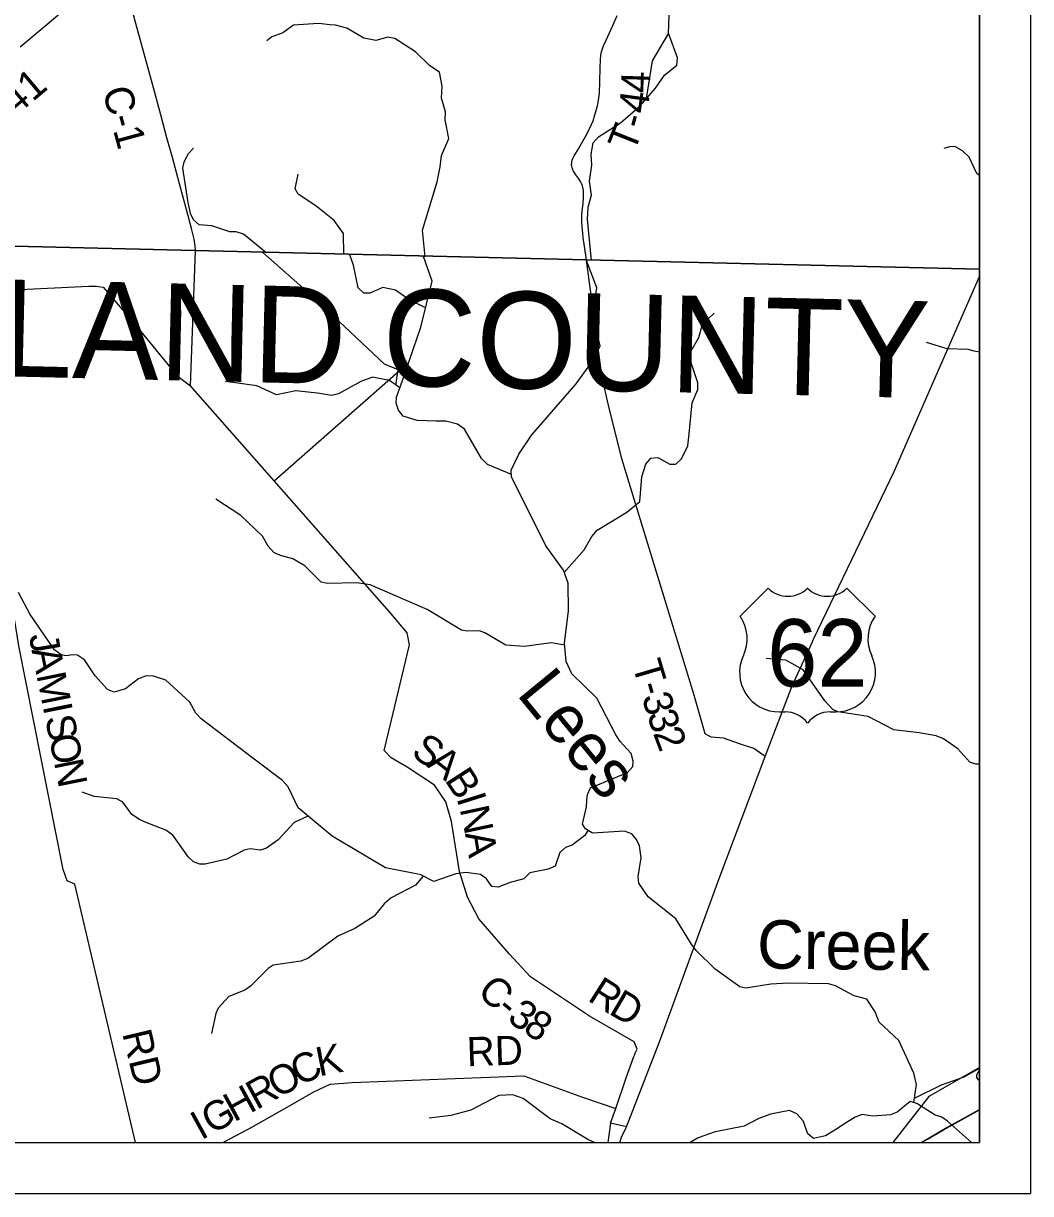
# Model space of a CAD drawing. Extents: x 0 to 34, y 0 to 22.
# Drawn here: x 7.032 to 9, y 14 to 16.287 of the extents above; entities that cross this region are included whole.
import ezdxf

# ---------------------------------------------------------------- set-up
doc = ezdxf.new("R2010")
doc.units = 0
for name, color, linetype in [('Default', 7, 'Continuous'), ('GM_X_City_Street', 7, 'Continuous'), ('GM_X_County_Road', 7, 'Continuous'), ('GM_X_County_Road_Text', 7, 'Continuous'), ('GM_X_County_Text', 7, 'Continuous'), ('GM_X_Minor_River', 7, 'Continuous'), ('GM_X_Minor_River_Text', 7, 'Continuous'), ('GM_X_State_Route', 7, 'Continuous'), ('GM_X_Township_Road', 7, 'Continuous'), ('GM_X_Township_Road_Text', 7, 'Continuous'), ('GM_X_US_Location', 7, 'Continuous'), ('GM_X_US_Route', 7, 'Continuous'), ('GM_X_US_Shield', 7, 'Continuous'), ('SH_Cut_Line', 7, 'Continuous'), ('SH_Data', 7, 'Continuous')]:
    doc.layers.add(name, color=color, linetype=linetype)

msp = doc.modelspace()

# ---------------------------------------------------------------- linework, layer by layer
at = {"layer": 'Default'}
for points in [[(8.9, 15.8067), (8.9, 19.2947), (8.3519, 19.0632), (7.2653, 18.6041), (6.6732, 18.3539), (6.6309, 18.3364), (6.5451, 17.2211), (6.5428, 17.1931), (6.4392, 15.8657), (6.5786, 15.8624), (7.3679, 15.8435), (8.1324, 15.8252)], [(4.022, 14.1), (8.9, 14.1), (8.9, 15.8067), (8.1324, 15.8252), (7.3679, 15.8435), (6.5786, 15.8624), (6.4392, 15.8657), (6.2834, 15.7529), (6.0871, 15.6176), (5.6165, 15.2674), (4.302, 14.3105), (4.1658, 14.2105)], [(8.9, 14.1643), (8.9, 14.2464), (8.8015, 14.1899), (8.7312, 14.1), (8.786, 14.1), (8.7983, 14.1072), (8.8295, 14.125)]]:
    msp.add_lwpolyline(points, close=True, dxfattribs=at)
at = {"layer": 'GM_X_City_Street'}
msp.add_lwpolyline([(8.9, 14.2204), (8.898, 14.2221), (8.8947, 14.2267), (8.8949, 14.2319), (8.9, 14.2417)], dxfattribs=at)
at = {"layer": 'GM_X_County_Road'}
for points in [[(7.3682, 15.843), (7.3678, 15.8535), (7.3674, 15.8566), (7.3657, 15.8658), (7.3612, 15.8839), (7.3542, 15.911), (7.3374, 15.974), (7.3234, 16.025), (7.3126, 16.0639), (7.3006, 16.1089), (7.2846, 16.1689), (7.2755, 16.2019), (7.2631, 16.2468), (7.2541, 16.2798), (7.2411, 16.3277), (7.2279, 16.3757), (7.2233, 16.3937), (7.221, 16.4018), (7.2199, 16.4064)], [(8.2278, 14.2742), (8.2312, 14.2825), (8.2252, 14.2966), (8.1384, 14.347), (8.0228, 14.4237), (7.9819, 14.4677), (7.9219, 14.5373), (7.8997, 14.5792), (7.884, 14.6295), (7.8686, 14.7276), (7.8578, 14.7657), (7.8352, 14.7985), (7.7821, 14.8334), (7.751, 14.8519), (7.737, 14.8664), (7.7538, 14.9366), (7.7866, 15.0728), (7.7818, 15.096), (7.7478, 15.1369), (7.522, 15.3933), (7.3588, 15.5787), (7.3682, 15.843)], [(8.2107, 14.1307), (8.1793, 14.1375), (8.1894, 14.1666), (8.21, 14.2261), (8.2251, 14.2678), (8.2262, 14.2705), (8.2278, 14.2742)], [(8.1975, 14.1), (8.2011, 14.1101), (8.2107, 14.1307)]]:
    msp.add_lwpolyline(points, dxfattribs=at)
at = {"layer": 'GM_X_Minor_River'}
for points in [[(8.1422, 15.8241), (8.1346, 15.9045), (8.1356, 15.9284), (8.1419, 15.9518), (8.1384, 15.9788), (8.143, 16.0102), (8.1413, 16.0315), (8.1453, 16.0538), (8.1561, 16.0659), (8.1988, 16.0931), (8.2375, 16.1265), (8.267, 16.1611), (8.2851, 16.186), (8.3088, 16.2058), (8.3101, 16.2199), (8.2928, 16.2682), (8.2945, 16.3183)], [(7.8173, 15.831), (7.8122, 15.8834), (7.8405, 15.978), (7.8465, 16.0072), (7.8494, 16.0291), (7.8634, 16.0624), (7.8566, 16.0992), (7.8567, 16.1144), (7.8494, 16.1414), (7.8505, 16.1646), (7.8451, 16.1919), (7.8266, 16.2043), (7.7981, 16.2315), (7.7578, 16.2577), (7.7442, 16.2605), (7.7206, 16.2539), (7.6976, 16.2583), (7.6644, 16.278), (7.6417, 16.2839), (7.6315, 16.2848), (7.6088, 16.2869), (7.5599, 16.284), (7.5392, 16.269), (7.5175, 16.2613), (7.5076, 16.2534)], [(8.2928, 16.2682), (8.2608, 16.2143), (8.2492, 16.1404)], [(7.5055, 15.84), (7.4622, 15.8756), (7.4482, 15.8799), (7.4357, 15.8801), (7.4005, 15.8914), (7.3756, 15.8939), (7.3643, 15.9035), (7.3587, 15.9157), (7.3544, 15.9374), (7.3438, 16.0043), (7.3462, 16.0168), (7.3547, 16.0334), (7.3643, 16.0432)], [(8.9, 15.9902), (8.8949, 15.9938), (8.8801, 16.0262), (8.8669, 16.0385), (8.8523, 16.0466), (8.8413, 16.0464), (8.8306, 16.0431)], [(7.6581, 15.8355), (7.6578, 15.877), (7.6391, 15.9019), (7.6034, 15.9307), (7.5692, 15.9534), (7.5632, 15.9641), (7.5692, 15.9925)], [(7.7601, 15.5803), (7.7647, 15.6101), (7.7375, 15.6215), (7.5944, 15.7563), (7.5003, 15.8393)], [(7.8181, 15.7314), (7.7834, 15.7488), (7.759, 15.7662), (7.7343, 15.7711), (7.7091, 15.76), (7.6974, 15.7598), (7.6861, 15.7706), (7.6769, 15.8151), (7.6703, 15.8351)], [(7.7728, 15.5895), (7.8088, 15.6934), (7.8309, 15.7838), (7.814, 15.8316)], [(8.1125, 15.5828), (8.1473, 15.6315), (8.159, 15.6572), (8.1447, 15.7189), (8.1527, 15.7704), (8.1321, 15.8238)], [(8.3499, 15.5845), (8.3366, 15.624), (8.3345, 15.6373), (8.3366, 15.6472), (8.3517, 15.6735), (8.3593, 15.6996), (8.3816, 15.721)], [(8.9, 15.6445), (8.8896, 15.6468), (8.8779, 15.65), (8.8369, 15.6514), (8.7969, 15.6637)], [(7.7674, 15.5748), (7.7477, 15.5895), (7.7143, 15.5958), (7.6914, 15.5877), (7.6476, 15.5633), (7.6343, 15.5601), (7.607, 15.5647), (7.5648, 15.5692), (7.527, 15.5614), (7.4881, 15.5791), (7.427, 15.5876)], [(7.9858, 15.4054), (7.9388, 15.4255), (7.9272, 15.4367), (7.8938, 15.4942), (7.8803, 15.5043), (7.8576, 15.5096), (7.8378, 15.5099), (7.8017, 15.5112), (7.774, 15.5196), (7.7651, 15.5315), (7.7603, 15.5449), (7.7609, 15.557), (7.7728, 15.5895)], [(8.7716, 14.1778), (8.7769, 14.2132), (8.7716, 14.2357), (8.7429, 14.2992), (8.7039, 14.3351), (8.6962, 14.3554), (8.6799, 14.3803), (8.6552, 14.3864), (8.6186, 14.406), (8.605, 14.4103), (8.5267, 14.4115), (8.4924, 14.4094), (8.4436, 14.4014), (8.4322, 14.4039), (8.384, 14.4384), (8.3466, 14.4751), (8.3376, 14.4874), (8.3072, 14.5369), (8.2527, 14.5803), (8.2349, 14.6068), (8.2332, 14.6197), (8.2391, 14.6561), (8.2357, 14.6801), (8.2301, 14.6923), (8.2208, 14.7031), (8.2068, 14.7083), (8.144, 14.7043), (8.1304, 14.7128), (8.1245, 14.7224), (8.1322, 14.7557), (8.1332, 14.7683), (8.1341, 14.78), (8.1404, 14.7929), (8.2124, 14.8233), (8.2229, 14.8349), (8.2238, 14.8455), (8.2195, 14.8604), (8.1981, 14.8835), (8.19, 14.897), (8.1527, 14.9682), (8.104, 15.0157), (8.0929, 15.0402), (8.0897, 15.0759), (8.0975, 15.1389), (8.0965, 15.1932), (8.0874, 15.2185), (8.0531, 15.2665), (8.0465, 15.2799), (7.986, 15.4005), (7.9854, 15.4138), (8, 15.4455), (8.0257, 15.4831), (8.1125, 15.5828)], [(8.089, 15.2139), (8.1279, 15.2585), (8.1428, 15.2845), (8.1533, 15.2969), (8.2112, 15.3321), (8.2363, 15.3526), (8.2405, 15.4008), (8.2481, 15.4257), (8.2578, 15.4374), (8.2715, 15.4391), (8.2949, 15.4258), (8.3071, 15.426), (8.3183, 15.4365), (8.3301, 15.4617), (8.3318, 15.4735), (8.3327, 15.4852), (8.3386, 15.5456), (8.3497, 15.572), (8.3499, 15.5845)], [(8.0901, 15.0717), (8.0634, 15.0763), (8.0112, 15.0695), (7.9747, 15.072), (7.934, 15.0962), (7.9234, 15.0998), (7.8991, 15.0997), (7.8881, 15.1011), (7.8214, 15.142), (7.7099, 15.19), (7.6829, 15.1939), (7.6262, 15.1928), (7.6137, 15.1949), (7.5819, 15.2273), (7.5585, 15.241), (7.5343, 15.247), (7.5218, 15.2533), (7.5106, 15.2653), (7.4991, 15.2852), (7.4571, 15.3257), (7.4085, 15.3572)], [(8.1353, 14.7098), (8.1291, 14.6999), (8.1044, 14.6813), (8.0914, 14.6766), (8.0802, 14.6665), (8.0711, 14.64), (8.0577, 14.6342), (8.0214, 14.6267), (8.0102, 14.6155), (7.9835, 14.6083), (7.9601, 14.5988), (7.9472, 14.6001), (7.9371, 14.6151), (7.9251, 14.624), (7.8974, 14.6279), (7.8768, 14.6248), (7.834, 14.6098), (7.8087, 14.6228), (7.7966, 14.626), (7.7397, 14.6367), (7.6356, 14.6987), (7.5688, 14.7541), (7.5493, 14.7954), (7.5384, 14.8074), (7.4831, 14.8492), (7.3794, 14.928), (7.3693, 14.9391), (7.3574, 14.9606), (7.3106, 15.0039), (7.2845, 15.0122), (7.2708, 15.0117), (7.2573, 15.0062), (7.2315, 14.9865), (7.2098, 14.98), (7.1965, 14.9855), (7.1726, 15.0124), (7.1514, 15.0435), (7.1379, 15.0525), (7.1284, 15.053), (7.1161, 15.0509), (7.1059, 15.0534), (7.0931, 15.0627), (7.0455, 15.1318), (7.0226, 15.1751)], [(8.9, 14.8391), (8.8932, 14.8391), (8.8815, 14.8434), (8.8576, 14.8693), (8.8301, 14.8887), (8.8157, 14.8946), (8.7824, 14.9004), (8.7326, 14.9065), (8.6828, 14.9327), (8.6232, 14.9416), (8.6134, 14.946), (8.5981, 14.9629), (8.556, 15.024), (8.5221, 15.0427), (8.4833, 15.046)], [(7.5882, 14.738), (7.5615, 14.7253), (7.5298, 14.6912), (7.5071, 14.6749), (7.4952, 14.6716), (7.4755, 14.6738), (7.4636, 14.671), (7.4299, 14.6536), (7.3875, 14.644), (7.3768, 14.6442), (7.3647, 14.6485), (7.3546, 14.6574), (7.3245, 14.7008), (7.3105, 14.7102), (7.2701, 14.726), (7.2588, 14.7315), (7.2444, 14.7408), (7.2266, 14.765), (7.2149, 14.7717), (7.1704, 14.7765), (7.147, 14.7849)], [(7.8136, 14.6202), (7.7985, 14.6032), (7.7509, 14.578), (7.7374, 14.5665), (7.7173, 14.5421), (7.6796, 14.518), (7.6463, 14.5029), (7.5881, 14.4597), (7.574, 14.4546), (7.5202, 14.4467), (7.5102, 14.44), (7.4762, 14.4056), (7.4647, 14.3978), (7.4337, 14.3853), (7.4131, 14.3625), (7.4084, 14.3523), (7.3998, 14.3129)], [(8.7729, 14.1865), (8.826, 14.2124), (8.87, 14.2285), (8.9, 14.2449)], [(8.148, 14.1), (8.135, 14.1056), (8.0841, 14.1364), (8.0611, 14.1462), (8.0088, 14.1858), (7.9887, 14.1929), (7.9613, 14.1918), (7.9061, 14.163), (7.8675, 14.1526), (7.8248, 14.1476)], [(8.8844, 14.1), (8.8378, 14.1416), (8.8269, 14.1493), (8.8137, 14.1533), (8.7779, 14.1759), (8.7646, 14.1799), (8.7396, 14.1594), (8.7262, 14.1539), (8.6919, 14.1514), (8.671, 14.1548), (8.6572, 14.1496), (8.633, 14.1344), (8.623, 14.1274), (8.5992, 14.1129), (8.5759, 14.1076), (8.565, 14.1165), (8.5559, 14.1425), (8.5436, 14.156), (8.5292, 14.1622), (8.4922, 14.1552), (8.4689, 14.1465), (8.4405, 14.1321), (8.384, 14.1208)], [(8.384, 14.1208), (8.3507, 14.1087), (8.3349, 14.1)]]:
    msp.add_lwpolyline(points, dxfattribs=at)
at = {"layer": 'GM_X_State_Route'}
msp.add_lwpolyline([(8.7872, 14.1), (8.7985, 14.1067), (8.8297, 14.1244), (8.9, 14.1637)], dxfattribs=at)
at = {"layer": 'GM_X_Township_Road'}
for p, q in [((7.522, 15.3933), (7.7655, 15.6077)), ((8.1793, 14.1375), (8.1738, 14.1))]:
    msp.add_line(p, q, dxfattribs=at)
for points in [[(7.0258, 16.2416), (7.0544, 16.2655), (7.0781, 16.2854), (7.1042, 16.3075), (7.1303, 16.3297), (7.1562, 16.3518), (7.1866, 16.3785), (7.2079, 16.3962), (7.2152, 16.4024), (7.2199, 16.4064)], [(8.1326, 15.8246), (8.1312, 15.8344), (8.128, 15.8559), (8.1261, 15.8682), (8.1251, 15.8774), (8.1239, 15.8898), (8.1235, 15.9022), (8.1235, 15.9115), (8.1241, 15.9208), (8.1251, 15.9301), (8.1259, 15.9362), (8.1265, 15.9455), (8.1266, 15.9548), (8.1263, 15.961), (8.1259, 15.9641), (8.1253, 15.9672), (8.1246, 15.9701), (8.1235, 15.9731), (8.1222, 15.9759), (8.1206, 15.9785), (8.1171, 15.9836), (8.1114, 15.9911), (8.1081, 15.9963), (8.1066, 15.999), (8.1054, 16.0019), (8.1045, 16.0048), (8.1038, 16.0079), (8.1034, 16.011), (8.1035, 16.0141), (8.1038, 16.0171), (8.1046, 16.0201), (8.1057, 16.023), (8.1086, 16.0285), (8.1149, 16.0392), (8.1228, 16.0526), (8.1305, 16.0661), (8.1378, 16.0798), (8.1418, 16.0882), (8.1452, 16.0969), (8.149, 16.1087), (8.1531, 16.1236), (8.1552, 16.1327), (8.1567, 16.1419), (8.1575, 16.1512), (8.1582, 16.1729), (8.1588, 16.2008), (8.1598, 16.2163), (8.1607, 16.2256), (8.1618, 16.2317), (8.1634, 16.2377), (8.1655, 16.2435), (8.1706, 16.2548), (8.1837, 16.283), (8.1925, 16.3029)], [(8.4816, 14.8541), (8.4594, 14.8701), (8.4313, 14.8794), (8.3998, 14.8903), (8.3762, 14.8923), (8.364, 14.8989), (8.3421, 14.9765), (8.2014, 15.4365), (8.1754, 15.5412), (8.1628, 15.5949), (8.1326, 15.8246)], [(6.5453, 15.7486), (6.9318, 15.7625), (7.1599, 15.7735), (7.1747, 15.774), (7.1884, 15.7718), (7.2556, 15.692), (7.3321, 15.5994), (7.3588, 15.5787)], [(7.2512, 14.1), (7.1325, 14.605), (7.1181, 14.6116), (7.1099, 14.6333), (7.0235, 15.0709), (7.0125, 15.1398), (6.9982, 15.225), (6.8762, 15.3717), (6.6676, 15.6148), (6.5583, 15.7333), (6.5453, 15.7486)], [(7.4222, 14.1), (7.4725, 14.1263), (7.5478, 14.1691), (7.5982, 14.1984), (7.6314, 14.2138), (7.6748, 14.2169), (8.0102, 14.23), (8.1245, 14.1886), (8.1894, 14.1666)]]:
    msp.add_lwpolyline(points, dxfattribs=at)
at = {"layer": 'GM_X_US_Route'}
for points in [[(8.5761, 15.0835), (8.7336, 15.4115), (8.9, 15.7927)], [(8.2107, 14.1307), (8.2747, 14.2969), (8.3917, 14.6157), (8.4816, 14.8541), (8.5339, 14.9928), (8.5731, 15.0772), (8.5761, 15.0835)], [(8.1975, 14.1), (8.2011, 14.1101), (8.2107, 14.1307)]]:
    msp.add_lwpolyline(points, dxfattribs=at)
at = {"layer": 'GM_X_US_Shield'}
for p, q in [((8.4873, 15.1834), (8.4324, 15.1284)), ((8.6961, 15.1284), (8.6411, 15.1834)), ((8.5093, 14.9417), (8.5203, 14.9417)), ((8.6082, 14.9417), (8.6192, 14.9417))]:
    msp.add_line(p, q, dxfattribs=at)
for centre, radius, start, end in [((8.5258, 15.2226), 0.0549, 225.573, 314.427), ((8.6027, 15.2226), 0.0549, 225.573, 314.427), ((8.3694, 15.0843), 0.0769, 334.5471, 35.0009), ((8.7591, 15.0843), 0.0769, 144.9991, 205.4529), ((8.5084, 15.0186), 0.0769, 154.8319, 270.6383), ((8.62, 15.0186), 0.0769, 269.3617, 25.1681), ((8.5203, 14.8867), 0.0549, 36.8699, 90), ((8.6082, 14.8867), 0.0549, 90, 143.1301)]:
    msp.add_arc(centre, radius, start, end, dxfattribs=at)
at = {"layer": 'SH_Cut_Line'}
msp.add_lwpolyline([(6.6654, 18.7733), (6.6363, 18.3979), (6.6309, 18.3364), (6.5451, 17.2211), (6.5428, 17.1931), (6.4392, 15.8657), (6.5786, 15.8624), (7.3679, 15.8435), (8.1324, 15.8252), (8.9, 15.8067), (8.9, 20.9), (6.8302, 20.9), (6.6949, 19.1537), (6.6858, 19.0362)], dxfattribs=at)
at = {"layer": 'SH_Data'}
for p, q in [((9, 21), (9, 14)), ((8.9, 20.9), (8.9, 14.1)), ((2.1, 14.1), (8.9, 14.1)), ((2, 14), (9, 14))]:
    msp.add_line(p, q, dxfattribs=at)

# ---------------------------------------------------------------- texts
at = {"layer": 'GM_X_County_Road_Text'}
for s, height, rotation, p in [('C-1', 0.05682, 285.2627, (7.1861, 16.1563)), ('S', 0.0568, 326.1887, (7.7874, 14.8568)), ('A', 0.0568, 321.5052, (7.8183, 14.8362)), ('B', 0.0568, 303.0373, (7.8542, 14.8086)), ('I', 0.0568, 287.64, (7.8779, 14.7731)), ('N', 0.0568, 281.9329, (7.8846, 14.7524)), ('A', 0.0568, 279.3929, (7.8948, 14.7041)), ('C', 0.0568, 315.4118, (7.9166, 14.3929)), ('R', 0.0568, 327.6545, (8.1325, 14.3786)), ('D', 0.0568, 329.594, (8.1737, 14.3526)), ('-', 0.0568, 320.0191, (7.9535, 14.3567)), ('3', 0.0568, 324.6265, (7.9753, 14.3387)), ('8', 0.0568, 326.9302, (8.0059, 14.317))]:
    msp.add_text(s, height=height, rotation=rotation, dxfattribs=at).set_placement(p)
at = {"layer": 'GM_X_County_Text'}
msp.add_text('HIGHLAND COUNTY', height=0.189394, rotation=358.6406, dxfattribs=at).set_placement((6.3531, 15.6128))
at = {"layer": 'GM_X_Minor_River_Text'}
for s, rotation, p in [('Lees', 309.3395, (7.9941, 14.9764)), ('Creek', 359.3406, (8.4652, 14.4402))]:
    msp.add_text(s, height=0.09469, rotation=rotation, dxfattribs=at).set_placement(p)
at = {"layer": 'GM_X_Township_Road_Text'}
for s, height, rotation, p in [('T-41', 0.05682, 40.2581, (6.9634, 16.0596)), ('4', 0.0568, 88.2553, (8.2561, 16.1506)), ('4', 0.0568, 82.2291, (8.2508, 16.1094)), ('-', 0.0568, 74.73, (8.2431, 16.079)), ('T', 0.0568, 68.306, (8.2252, 16.0329)), ('J', 0.0568, 279.6689, (7.0431, 15.0909)), ('A', 0.0568, 281.1941, (7.0479, 15.063)), ('T', 0.0568, 286.4858, (8.2213, 15.0343)), ('M', 0.0568, 281.344, (7.0576, 15.0138)), ('-', 0.0568, 286.4794, (8.2334, 14.9936)), ('3', 0.0568, 286.5848, (8.24, 14.9711)), ('I', 0.0568, 281.3467, (7.0697, 14.9533)), ('3', 0.0568, 287.4348, (8.2503, 14.9367)), ('S', 0.0568, 281.3388, (7.0743, 14.9305)), ('O', 0.0568, 281.3443, (7.0819, 14.8929)), ('2', 0.0568, 290.5908, (8.2619, 14.9001)), ('N', 0.0568, 281.3407, (7.0917, 14.8439)), ('RD', 0.05682, 283.4381, (7.2251, 14.3134)), ('RD', 0.05682, 1.9738, (7.8993, 14.2488)), ('C', 0.0568, 26.8007, (7.5721, 14.2092)), ('K', 0.0568, 11.2442, (7.6099, 14.2289)), ('O', 0.0568, 28.5985, (7.5286, 14.1854)), ('R', 0.0568, 28.7195, (7.4877, 14.163)), ('H', 0.0568, 28.7238, (7.4439, 14.139)), ('G', 0.0568, 28.7192, (7.4, 14.115)), ('I', 0.0568, 28.7195, (7.3795, 14.1038))]:
    msp.add_text(s, height=height, rotation=rotation, dxfattribs=at).set_placement(p)
at = {"layer": 'GM_X_US_Location'}
for s, p in [('0', (8.5641, 15.056)), ('/', (8.5642, 15.056))]:
    msp.add_text(s, height=0.000189, dxfattribs=at).set_placement(p)
msp.add_text('62', height=0.000189, rotation=0, dxfattribs=at).set_placement((8.5251, 15.0168))
at = {"layer": 'GM_X_US_Shield'}
msp.add_text('62', height=0.13184, dxfattribs=at).set_placement((8.4854, 14.9911))

doc.saveas('drawing.dxf')
